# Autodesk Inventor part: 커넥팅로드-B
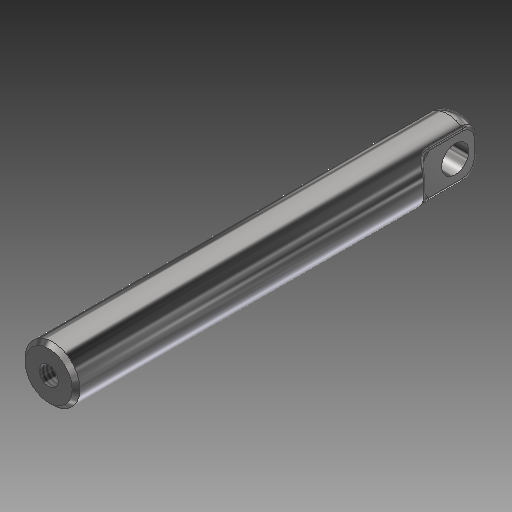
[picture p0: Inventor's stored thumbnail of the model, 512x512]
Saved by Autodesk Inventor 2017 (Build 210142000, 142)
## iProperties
Created: 2018-01
Part Number: 커넥팅로드-B
Material: 강철, 연강
Document SubType Name: Modeling
Designer: mduedu
Density: 7.86 g/cm^3
Mass: 14.5817 g
Surface Area: 12.9187 cm^2
Volume: 1.85518 cm^3
Appearance: 반광택
Author: mduedu
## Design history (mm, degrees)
sketch "스케치1"
  geometry: C1 r 3.5 at (0, 0); 1 further point
  constraints: 1 centre point, 1 coincident
  dimensions: "d0" = 7 diameter of C1
extrude "돌출1" new body sketch "스케치1" distance "d1" = 53; taper "d2" = 0 deg
node "작업 평면1"
sketch "스케치2"
  geometry: L1 (-3.5, 0)-(3.5, 0) reference; L2 (4, 4)-(4, 0); L3 (4, 0)-(-4, 0); L4 (-4, 0)-(-4, 4); A1 r 4 centre (0, 4) between (4, 4) and (-4, 4); 2 further points
  constraints: 6 end point, 2 perpendicular, 2 point on circle, 2 tangent, 1 centre point, 1 collinear, 1 midpoint, 1 vertical, 1 vertical alignment
  dimensions: "d4" = 8 diameter of A1; "d5" = 4 distance from line of A1.centre L1
extrude "돌출2" cut sketch "스케치2" stored distance "d6" = 53; taper "d7" = 0 deg
fillet "모깎기1" dims "d8" = 2
fillet "모깎기2" dims "d9" = 0.5
fillet "모깎기3" dims "d10" = 0.5
sketch "스케치3"
  geometry: C1 r 1.75 at (0, 3); 1 further point
  constraints: 1 centre point, 1 vertical alignment
  dimensions: "d11" = 3.5 diameter of C1; "d12" = 3 distance of point (0, 0) C1.centre
extrude "돌출3" cut sketch "스케치3" stored distance "d13" = 53; taper "d14" = 0 deg
chamfer "모따기1" distance "d15" = 0.5; stored, may be unused: second distance "d16" = 2, angle "d17" = 45 deg
sketch "스케치4"
  geometry: 1 further point
hole "구멍1" sketch "스케치4" at (0, 0) diameter "d18" = 2.459; stored, may be unused: countersink angle "d22" = 90 deg, drill point angle "d24" = 120 deg; dims "d19" = 6.9, "d20" = 4, "d21" = 2, "d23" = 8.4
node "솔리드1"
mirror "대칭1"
other parameters: "d3" = 2
